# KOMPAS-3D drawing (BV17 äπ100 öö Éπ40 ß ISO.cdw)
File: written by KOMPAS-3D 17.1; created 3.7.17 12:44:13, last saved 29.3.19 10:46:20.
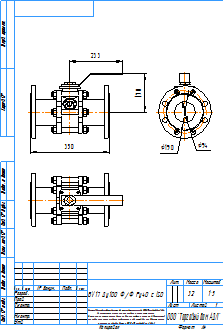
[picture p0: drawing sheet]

Sheet 1: A4, portrait

Title block, sheet 1: name: BV17 Ду100 Ф/Ф Ру40 с ISO; material: Сталь 20  ГОСТ 1050-88; mass: 32; sheets: 1; sheet format: A4; stored path: C:\Users\kka\KOMPAS_Work\!Trash\СС02 СС03 ФФ Смотровые стекла\СС01.cdw

Views: Спереди 1, Проекционный вид 2, Проекционный вид 3
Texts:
  Klimkovich
  ADL
  Рама для чертежей
  Лит-Масса-Масштаб
  Материал-Предприятие
  Масштаб
  Изм.
  Лист
  № докум.
  Подп.
  Дата
  Лит.
  Разраб.
  Пров.
  Т.контр.
  Листов
  Внимание! Данный продукт является объектом авторского права ООО «Торговый Дом АДЛ».
  Запрещается изменение, копирование, распространение
  (в том числе путем копирования на другие сайты и ресурсы в Интернете)
  или любое иное использование информации и объектов без предварительного
  согласия правообладателя (ООО «Торговый Дом АДЛ»).
  Н.контр.
  Утв.
  ООО "Торговый дом АДЛ"
  Изменение
  Номер документа
  Подпись
  Обозначение документа
  Наименование изделия
  Масса изделия по ГОСТ 2.109-73
  Порядковый номер листа
  Общее количество листов в документе
  Характер работы, выполненной лицом, подписавшим документ
  Наименование или индекс предприятия, выпускающего документ
  Инв. № подл.
  Подп. и дата
  Взам. инв. №
  Инв. № дубл.
  Инвентарный номер подлинника по ГОСТ 2.501-68
  Подпись принявшего подлинник в отдел технической документации
  Инвентарный номер подлинника, взамен которого выпущен данный подлинник
  Инвентарный номер дубликата по ГОСТ 2.502-68
  Подпись принявшего дубликат в отдел технической документации
  Справ. №
  Перв. примен.
  Обозначение документа, взамен или на основании которого выпущен данный документ
  Обозначение документа, в котором впервые записан данный документ
  Подпись лица, копировавшего чертеж
  Обозначение формата листа
  !Рама для чертежа
Dimensions and other numbers on the sheet: 233; 350; 170; 190; 94; 1:5; 1; 32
